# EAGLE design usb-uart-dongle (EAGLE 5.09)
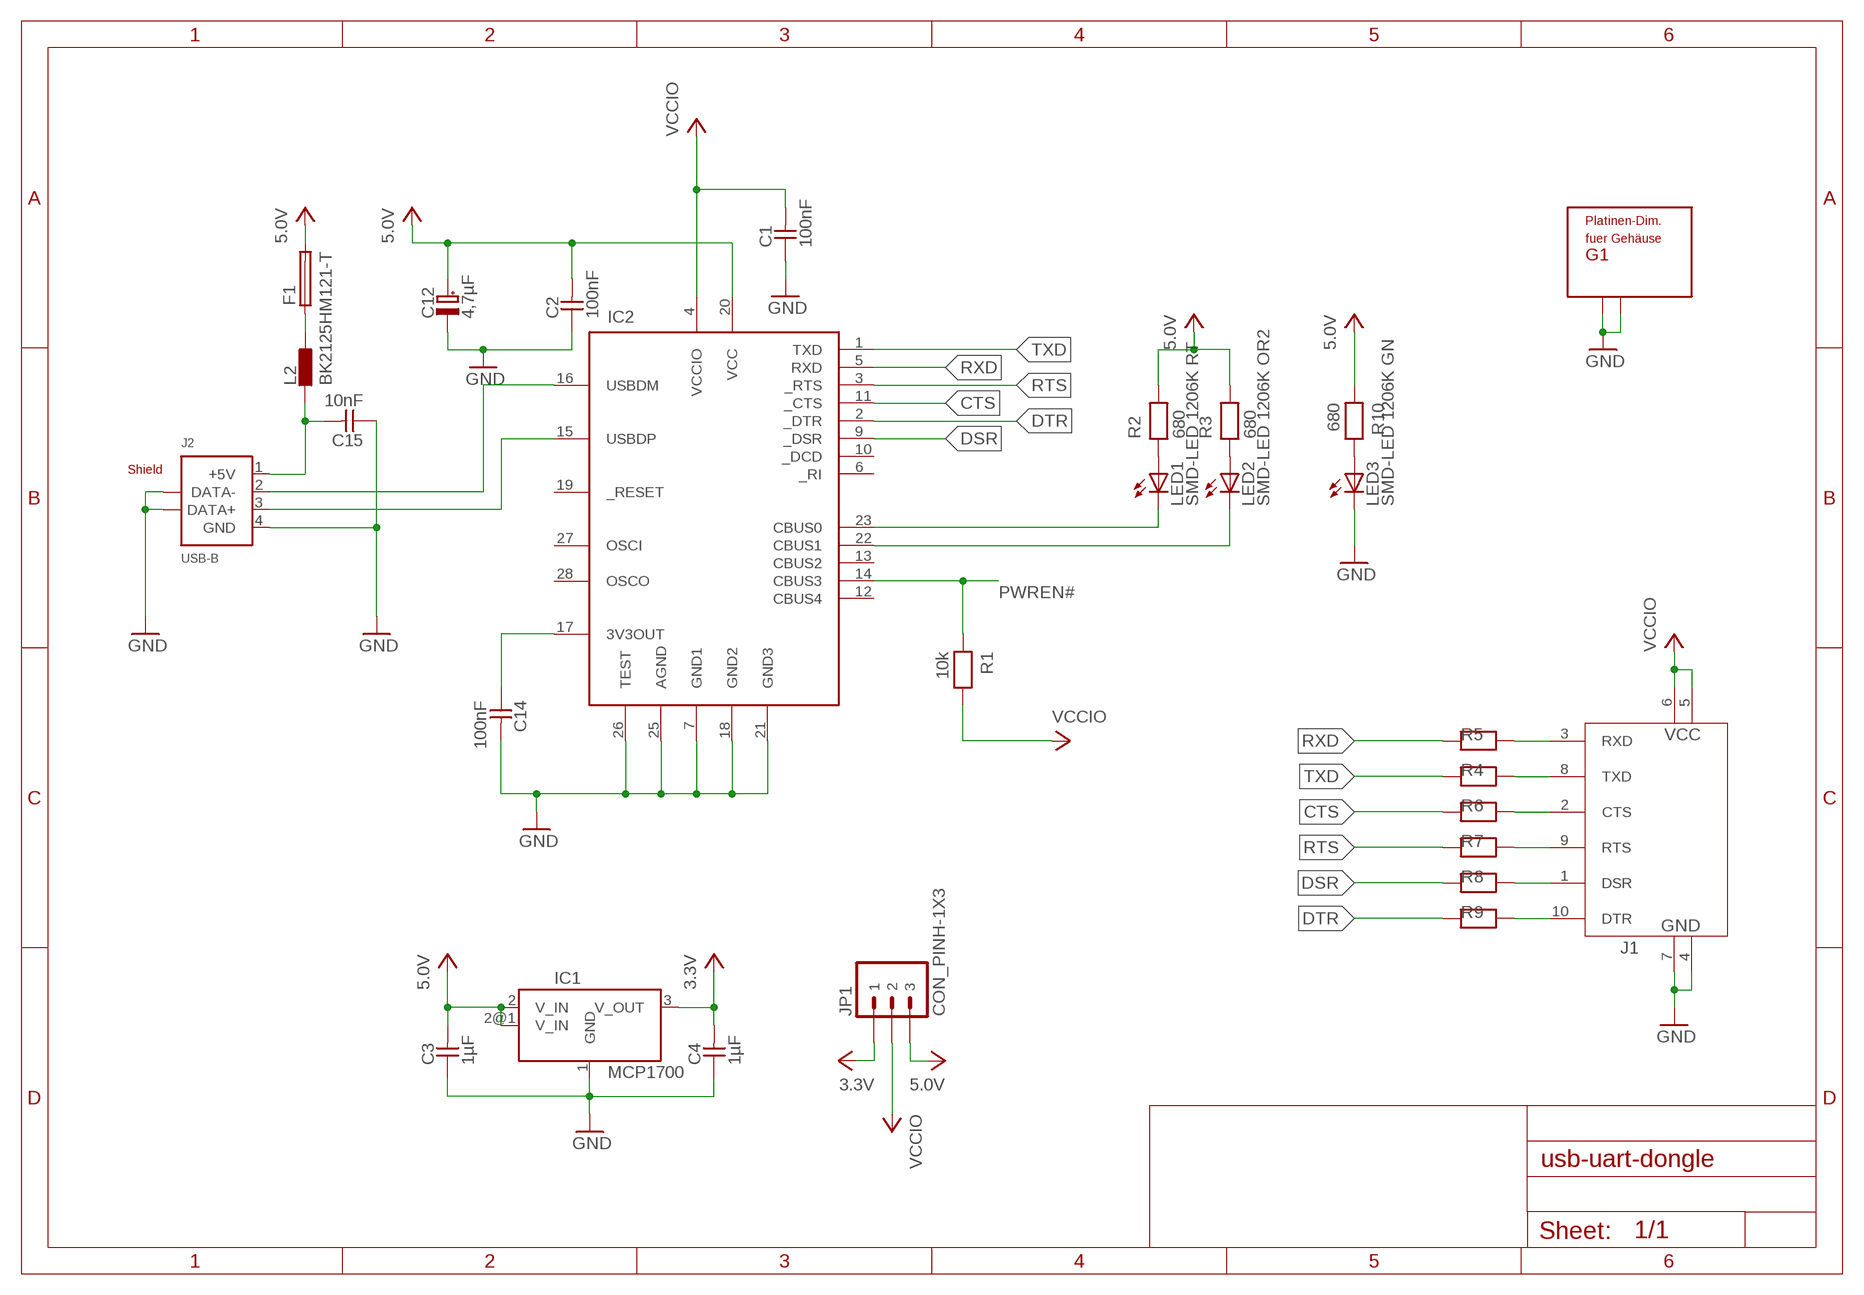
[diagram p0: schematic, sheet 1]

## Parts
C1  100nF  CAP-SMD-0805  [0805]
C2  100nF  CAP-SMD-0805  [0805]
C3  1µF  CAP-SMD-0805  [0805]
C4  1µF  CAP-SMD-0805  [0805]
C12  4,7µF  CAP-POL6032  [C-C/6032]
C14  100nF  CAP-SMD-0805  [0805]
C15  10nF  CAP-SMD-0805  [0805]
F1  SICHERUNG  [SICHERUNG-SMD-HASF-HALTER]
G1  GEHAEUSE_2GND  [GEH_TEKO_10006]
IC1  MCP1700  [SOT89]
IC2  FT232RL  [SSOP28DB]
J1  RS232_10PINHW  [ML10L]
J2  USB-B  [USB-B]
JP1  CON_PINH-1X3  [CON-1X3_PINH]
L2  BK2125HM121-T  L_0805  [R0805]
LED1  SMD-LED 1206K RT  LEDCHIP-LED1206  [CHIPLED_1206]
LED2  SMD-LED 1206K OR2  LEDCHIP-LED1206  [CHIPLED_1206]
LED3  SMD-LED 1206K GN  LEDCHIP-LED1206  [CHIPLED_1206]
R1  10k  RES0805  [0805]
R2  680  RES0805  [0805]
R3  680  RES0805  [0805]
R4  RES0805  [0805]
R5  RES0805  [0805]
R6  RES0805  [0805]
R7  RES0805  [0805]
R8  RES0805  [0805]
R9  RES0805  [0805]
R10  680  RES0805  [0805]

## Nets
3.3V: C4.2 IC1.3(V_OUT) JP1.1
5.0V: C2.2 C3.2 C12.+ F1.2 IC1.2(V_IN) IC1.2@1(V_IN) IC2.20(VCC) JP1.3 R2.2 R3.2 R10.1
5V_USB: C15.2 J2.1(+5V) L2.1
CTS: IC2.11(_CTS) R6.2
DSR: IC2.9(_DSR) R8.2
DTR: IC2.2(_DTR) R9.2
GND: C1.1 C2.1 C3.1 C4.1 C12.- C14.2 C15.1 G1.P$1 G1.P$3 IC1.1(GND) IC2.7(GND1) IC2.18(GND2) IC2.21(GND3) IC2.25(AGND) IC2.26(TEST) J1.4(GND) J1.7(GND) J2.4(GND) J2.S1 J2.S2 LED3.C
N$1: IC2.16(USBDM) J2.2(DATA-)
N$2: C14.1 IC2.17(3V3OUT)
N$3: LED1.A R2.1
N$4: LED2.A R3.1
N$5: J1.3(RXD) R5.2
N$6: J1.8(TXD) R4.1
N$7: LED3.A R10.2
N$8: J1.2(CTS) R6.1
N$9: J1.9(RTS) R7.1
N$10: IC2.15(USBDP) J2.3(DATA+)
N$11: J1.1(DSR) R8.1
N$12: J1.10(DTR) R9.1
N$21: F1.1 L2.2
PWREN#: IC2.14(CBUS3) R1.1
RTS: IC2.3(_RTS) R7.2
RXD: IC2.5(RXD) R5.1
RXLED: IC2.22(CBUS1) LED2.C
TXD: IC2.1(TXD) R4.2
TXLED: IC2.23(CBUS0) LED1.C
VCCIO: C1.2 IC2.4(VCCIO) J1.5(VCC) J1.6(VCC) JP1.2 R1.2
Unconnected: IC2.6(_RI) IC2.10(_DCD) IC2.12(CBUS4) IC2.13(CBUS2) IC2.19(_RESET) IC2.27(OSCI) IC2.28(OSCO)

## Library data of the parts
C1 C2 C14 C15 = CAN_BUS_Interface_v3:CAP-SMD: unipolare Kondensatoren
C3 C4 = firefly-lbr_v2:CAP-SMD: unipolare Kondensatoren
C12 = firefly-lbr_v2:CAP-POL: polare Kondensatoren
F1 = firefly-lbr_v2:SICHERUNG: Sicherung
G1 = lib-mechanic:GEHAEUSE_2GND
IC1 = firefly-lbr_v2:MCP1700: Spannungsregler SOT-89, benutzbar fuer MCP1700, HT7150-1
IC2 = firefly-lbr_v2:FT232RL: USB UART FT232RL 4th Generation USB UART (USB <-> Serial) Controller. aus der .lbr von Spark Fun Electronics
J1 = lib-com:RS232_10PIN
J2 = CAN_BUS_Interface_v3:USB: Universal-Seriel-Bus (USB) Steckverbinder Typ B
JP1 = scaleart:CON_PINH-1X3
L2 = lib-rcl:L
LED1-LED3 = lib-halbleiter:LED
R1-R3 R10 = firefly-lbr_v2:RES: Widerstand
R4-R9 = scaleart:RES: Widerstand

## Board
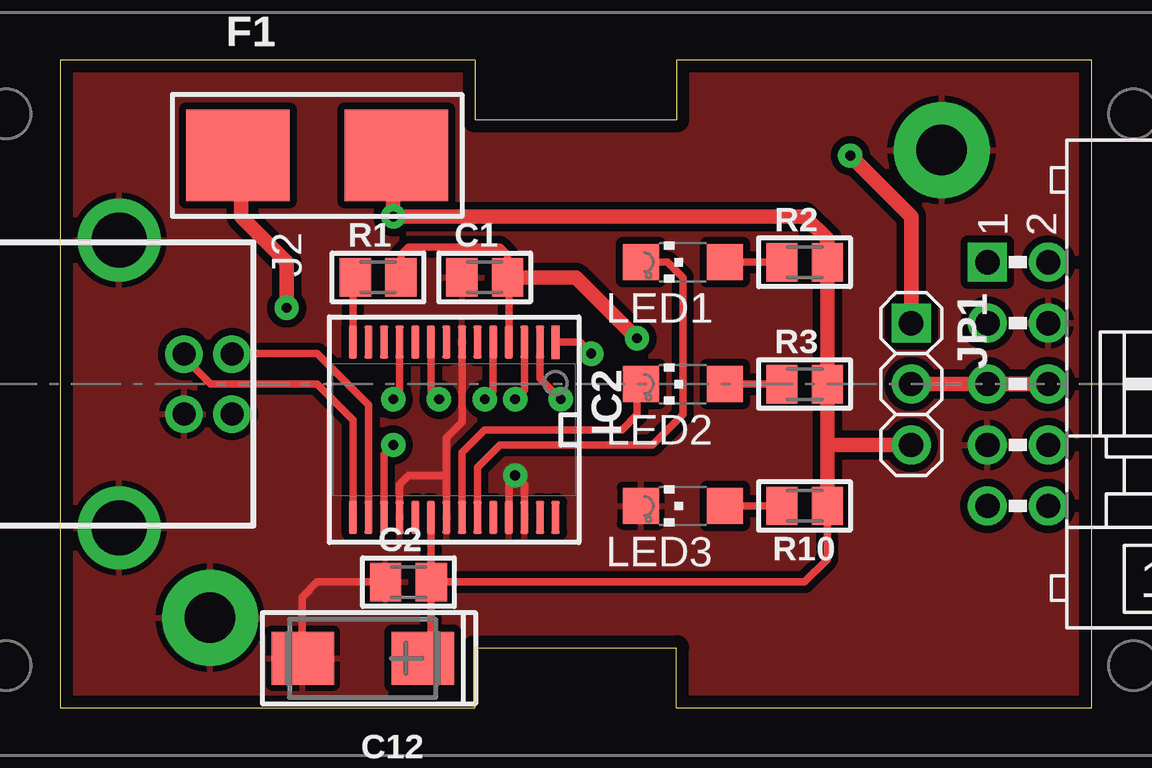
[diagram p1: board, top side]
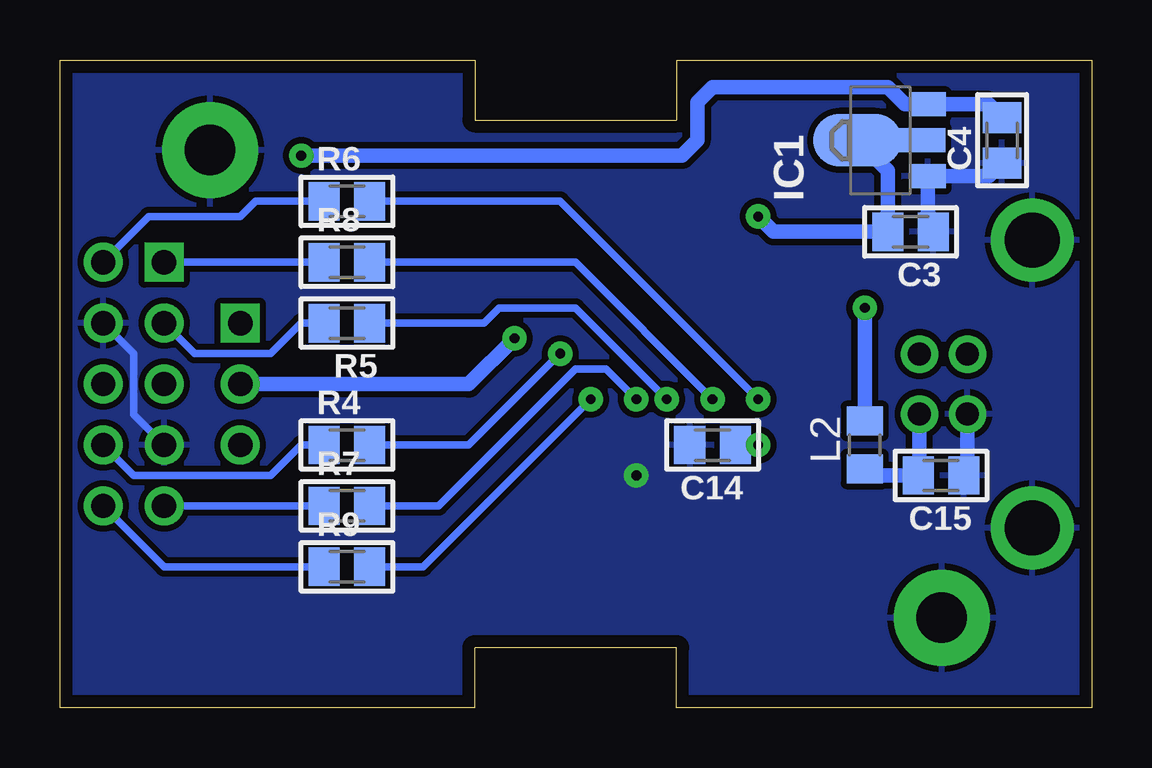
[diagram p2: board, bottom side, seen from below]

Size 43 x 27 mm. Coordinates in mm from the lower left corner, seen from the top.
Copper layers (1*16): Top 0.035mm / dielectric 1.5mm / Bottom 0.035mm
Design rules "lpt_ulm *": minimum track width 10mil, minimum drill 16mil, track to track 8mil, track to pad 8mil, pad to pad 8mil, via to via 8mil, smd to smd 4mil, copper to edge 20mil, drill to drill 8mil, minimum pad ring 12mil, minimum via ring 12mil, stop-mask expansion 4mil, vias tented up to drill 0mil, thermal gap 10mil
tRestrict: area 18.9,7.6 to 19.1,8.2

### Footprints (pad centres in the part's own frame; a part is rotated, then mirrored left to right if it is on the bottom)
0805 = smd 1.3 x 1.6: 1 -0.95,0; 2 0.95,0
C-C/6032 = smd 2.6 x 2.2: + -2.5,0; - 2.5,0
SICHERUNG-SMD-HASF-HALTER = smd 4.318 x 3.81: 1 -3.302,0; 2 3.302,0
GEH_TEKO_10006 = drill 2.1 pad 4 round: P$1 36.826,23.098; P$3 6.326,3.598
SOT89 = smd 1 x 1.5: 1 -1.499,-1.981; 3 1.499,-1.981 | smd 1 x 2: 2 0,-1.727 | smd 2.2 x 3.7: 2@1 0,0.94
SSOP28DB = smd 0.348 x 1.397: 1 -4.225,-3.656; 2 -3.575,-3.656; 3 -2.925,-3.656; 4 -2.275,-3.656; 5 -1.625,-3.656; 6 -0.975,-3.656; 7 -0.325,-3.656; 8 0.325,-3.656; 9 0.975,-3.656; 10 1.625,-3.656; 11 2.275,-3.656; 12 2.925,-3.656; 13 3.575,-3.656; 14 4.225,-3.656; 15 4.225,3.656; 16 3.575,3.656; 17 2.925,3.656; 18 2.275,3.656; 19 1.625,3.656; 20 0.975,3.656; 21 0.325,3.656; 22 -0.325,3.656; 23 -0.975,3.656; 24 -1.625,3.656; 25 -2.275,3.656; 26 -2.925,3.656; 27 -3.575,3.656; 28 -4.225,3.656
ML10L = drill 1.016 pad 1.626 square: 1 -5.08,-1.27 | drill 1.016 pad 1.626 round: 2 -5.08,1.27; 3 -2.54,-1.27; 4 -2.54,1.27; 5 0,-1.27; 6 0,1.27; 7 2.54,-1.27; 8 2.54,1.27; 9 5.08,-1.27; 10 5.08,1.27
USB-B = drill 0.95 round: 1 1.25,4.71; 2 -1.25,4.71; 3 -1.25,2.71; 4 1.25,2.71 | drill 2.3 pad 3 round: S1 -6,0; S2 6,0
CON-1X3_PINH = drill 1.016 pad 1.626 square: 1 -2.54,0 | drill 1.016 pad 1.626 round: 2 0,0; 3 2.54,0
R0805 = smd 1.2 x 1.5: 1 -1,0; 2 1,0
CHIPLED_1206 = smd 1.5 x 1.5: A 0,-1.75; C 0,1.75

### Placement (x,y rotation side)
C1  17.7,17.93 0 top
C2  14.53,5.23 0 top
C3  7.54,19.84 180 bottom
C4  3.73,23.65 90 bottom
C12  12.62,2.06 180 top
C14  15.8,10.95 180 bottom
C15  6.27,9.68 180 bottom
F1  10.72,23.01 0 top
G1  -0.08,0.15 0 top
IC1  8.81,23.65 90 bottom
IC2  16.43,11.58 180 top
J1  39.93,13.49 270 top
J2  2.46,13.49 270 top
JP1  35.48,13.49 270 top
L2  9.45,10.95 90 bottom
LED1  25.96,18.57 90 top
LED2  25.96,13.49 90 top
LED3  25.96,8.41 90 top
R1  13.26,17.93 0 top
R2  31.04,18.57 0 top
R3  31.04,13.49 0 top
R4  31.04,10.95 0 bottom
R5  31.04,16.03 180 bottom
R6  31.04,21.11 0 bottom
R7  31.04,8.41 0 bottom
R8  31.04,18.57 0 bottom
R9  31.04,5.87 0 bottom
R10  31.04,8.41 180 top

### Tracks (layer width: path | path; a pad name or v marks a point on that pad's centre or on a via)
3.3V  (via drill 0.41 pad 0.81)
  Top 0.61: JP1.1 35.48,20.47 v32.94,23.01
  Bottom 0.61: C4.2 4.28,25.15 IC1.3 7.77,25.15 8.5,25.87 15.8,25.87 16.43,25.23 16.43,23.65 17.07,23.01 v32.94,23.01
5.0V  (via drill 0.41 pad 0.81)
  Top 0.305: C12.+ 15.46,2.39 15.46,4.94 15.46,5.21 | 15.46,5.21 IC2.20 | R10.1 31.99,6.18 31.04,5.23 C2.2 15.46,5.21
  Top 0.61: R10.1 31.99,10.95 | 31.99,10.95 R3.2 R2.2 31.99,19.52 31.04,20.47 v13.89,20.47 13.89,22.89 F1.2 | 31.99,10.95 JP1.3
  Bottom 0.305: IC1.2@1 IC1.2
  Bottom 0.61: IC1.2@1 8.49,22.39 C3.2 13.26,19.84 v13.89,20.47
5V_USB
  Bottom 0.305: C15.2 7.17,9.73 | 9.18,9.68 L2.1
  Bottom 0.61: 7.17,9.73 J2.1 | C15.2 9.18,9.68
CTS  (via drill 0.41 pad 0.81)
  Top 0.305: IC2.11 14.16,13.12 v13.89,12.85
  Bottom 0.305: v13.89,12.85 22.15,21.11 R6.2
DSR  (via drill 0.41 pad 0.81)
  Top 0.305: IC2.9 15.46,13.19 v15.8,12.85
  Bottom 0.305: v15.8,12.85 21.51,18.57 R8.2
DTR  (via drill 0.41 pad 0.81)
  Top 0.305: IC2.2 20.01,13.72 v20.88,12.85
  Bottom 0.305: R9.2 27.86,5.87 v20.88,12.85
GND  (via drill 0.41 pad 0.81)
  Top 0.305: 16.11,9.68 IC2.21 | 16.11,9.68 16.11,11.26 16.76,11.91 IC2.7 | IC2.18 14.16,9.31 14.53,9.68 16.11,9.68 | C2.1 10.72,5.23 10.08,4.6 10.08,2.1 C12.- | IC2.25 18.71,9.41 v18.97,9.68 19.36,9.29 IC2.26
  Bottom 0.305: J1.4 39.93,14.76 39.93,12.22 J1.7 | C15.1 5.17,9.83 | C3.1 6.83,20.08
  Bottom 0.61: 5.17,9.83 J2.4 | C4.1 4.28,22.15 IC1.1 6.83,20.08
  pour Bottom (isolate 0.254): -0.08,27.15 -0.08,0.15 43.46,0.15 43.46,27.15
  pour Top (isolate 0.305): -0.08,27.15 -0.08,0.15 43.46,0.15 43.46,27.15
N$1
  Top 0.305: IC2.16 12.86,12.62 10.72,14.76 7.19,14.76 J2.2
N$2  (via drill 0.41 pad 0.81)
  Top 0.305: IC2.17 13.51,10.56 v13.89,10.95
  Bottom 0.305: v13.89,10.95 C14.1
N$3
  Top 0.305: LED1.A R2.1
N$4
  Top 0.305: LED2.A R3.1
N$5
  Bottom 0.305: R5.2 32.94,16.03 34.21,14.76 37.39,14.76 J1.3
N$6
  Bottom 0.305: R4.1 32.94,10.95 34.21,9.68 39.93,9.68 J1.8
N$7
  Top 0.305: LED3.A R10.2
N$8
  Bottom 0.305: R6.1 34.85,21.11 35.48,20.47 39.29,20.47 J1.2
N$9
  Bottom 0.305: R7.1 J1.9
N$10
  Top 0.305: J2.3 5.17,14.59 6.27,13.49 10.72,13.49 12.21,12 IC2.15
N$11
  Bottom 0.305: R8.1 J1.1
N$12
  Bottom 0.305: R9.1 38.66,5.87 J1.10
N$21  (via drill 0.41 pad 0.81)
  Top 0.305: 7.54,22.89 F1.1
  Top 0.61: 7.54,22.89 7.54,20.47 9.45,18.57 v9.45,16.66
  Bottom 0.61: L2.2 v9.45,16.66
PWREN#
  Top 0.305: IC2.14 12.21,17.83 R1.1
RTS  (via drill 0.41 pad 0.81)
  Top 0.305: IC2.3 19.36,13.24 v18.97,12.85
  Bottom 0.305: R7.2 27.23,8.41 21.51,14.12 20.24,14.12 v18.97,12.85
RXD  (via drill 0.41 pad 0.81)
  Top 0.305: IC2.5 18.06,13.21 v17.7,12.85
  Bottom 0.305: R5.1 25.32,16.03 24.69,16.66 21.51,16.66 v17.7,12.85
RXLED
  Top 0.305: IC2.22 16.76,10.64 17.7,11.58 23.42,11.58 24.05,12.22 24.05,13.33 LED2.C
TXD  (via drill 0.41 pad 0.81)
  Top 0.305: IC2.1 21.67,15.24 v22.15,14.76
  Bottom 0.305: R4.2 25.96,10.95 v22.15,14.76
TXLED
  Top 0.305: LED1.C 25.32,18.57 25.96,17.93 25.96,12.22 24.69,10.95 18.34,10.95 17.41,10.02 IC2.23
VCCIO  (via drill 0.41 pad 0.81)
  Top 0.305: R1.2 14.21,18.88 14.53,19.2 18.34,19.2 18.65,18.89 C1.2 18.71,17.88 IC2.4
  Top 0.61: J1.6 J1.5 JP1.2 | v24.05,15.39 21.51,17.93 C1.2
  Bottom 0.61: JP1.2 25.96,13.49 v24.05,15.39

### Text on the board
tStop: 3.3 | 5.0 | USB-UART | V2 27/02/2010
